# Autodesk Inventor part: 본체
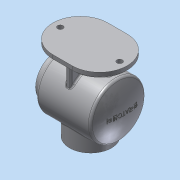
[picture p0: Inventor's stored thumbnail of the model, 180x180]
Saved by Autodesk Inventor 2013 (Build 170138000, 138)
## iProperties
Created: 2016-04
Part Number: 본체
Material: 알루미늄 6061
Document SubType Name: Modeling
Designer: dgall
Density: 1 g/cm^3
Author: dgall
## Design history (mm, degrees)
sketch "스케치1"
  geometry: L1 (-61, 0)-(61, 0); L2 (-61, 27)-(-46, 27); L3 (-46, 27)-(-46, 47); L4 (-46, 47)-(48.145, 47); L5 (-61, 27)-(-61, 38); L6 (-61, 38)-(-49, 38); L7 (-49, 38)-(-49, 50); L8 (-49, 50)-(50.087, 50); A1 r 120 centre (-59, 0) between (61, 0) and (50.087, 50); A2 r 117 centre (-59, 0) between (58, 0) and (48.145, 47); 2 further points
  constraints: 16 end point, 4 parallel, 4 point on circle, 3 perpendicular, 2 centre point, 2 point on line, 1 coincident, 1 concentric, 1 horizontal, 1 horizontal alignment, 1 midpoint, 1 vertical alignment
  dimensions: "d0" = 122 distance of L1.end L1.start; "d11" = 54 diameter of L2 L1; "d12" = 76 diameter of L6 L1; "d13" = 100 diameter of L8 L1; "d14" = 94 diameter of L4 L1; "d16" = 3 distance between parallel lines of L3 L7; "d99" = 120 radius of A1; "d101" = 3 distance of L1.end A2.start
revolve "회전1" sketch "스케치1" stored, may be unused: angle "d18" = 90 deg
node "작업 평면1"
sketch "스케치2"
  geometry: L1 (49.544, 50)-(49.544, -50) reference; C1 r 38 at (-0.456, 0); 1 further point
  constraints: 1 centre point, 1 horizontal alignment
  dimensions: "d104" = 50 distance from line of L1 C1.centre; "d105" = 76 diameter of C1
extrude "돌출1" join sketch "스케치2" distance "d23" = 15; taper "d25" = 0 deg; dims "d24" = 30, "d26" = 0
sketch "스케치13"
  geometry: L1 (61, 27)-(61, -27) reference; L2 (46, 47)-(46, -47) reference; L3 (-48.145, -47)-(46, -47) reference; L4 (61, 0)-(-58, 0); L5 (46, 0)-(46, -47); L6 (46, -47)-(-48.145, -47); A1 r 117 centre (59, 0) between (-48.145, 47) and (-48.145, -47) reference; A2 r 117 centre (59, 0) between (-58, 0) and (-48.145, -47); 1 further point
  constraints: 6 end point, 3 point on circle, 2 collinear, 2 midpoint, 1 centre point, 1 concentric, 1 point on line
revolve "회전4" sketch "스케치13" stored, may be unused: angle "d102" = 90 deg
node "작업 평면2"
sketch "스케치5"
  geometry: L1 (-17.5, 50)-(17.5, 50); L2 (-17.5, -50)-(17.5, -50); C1 r 5 at (54, 0); C2 r 5 at (-54, 0); A1 r 50 centre (-17.5, 0) between (-17.5, 50) and (-17.5, -50); A2 r 50 centre (17.5, 0) between (17.5, -50) and (17.5, 50); 1 further point
  constraints: 4 centre point, 4 end point, 4 horizontal alignment, 4 point on circle, 2 equal radius, 2 tangent, 1 horizontal, 1 parallel
  dimensions: "d34" = 135 dimension on A2 A1; "d36" = 50 radius of A1; "d37" = 17.5 distance of point (0, 0) A2.centre; "d38" = 10 diameter of C1; "d39" = 54 distance of point (0, 0) C1.centre; "d40" = 54 distance of C2.centre point (0, 0)
extrude "돌출3" join sketch "스케치5" distance "d41" = 10; taper "d42" = 0 deg
node "작업 평면3"
  node "작업축2"
sketch "스케치6"
  geometry: L1 (-49.544, -50)-(49.544, -50) reference; L2 (-18.044, -69)-(-68.044, -69) reference; L3 (66.956, -69)-(16.956, -69) reference; L4 (16.956, -69)-(-18.044, -69) reference; L5 (-68.044, -79)-(-68.044, -69) reference; L6 (66.956, -79)-(66.956, -69) reference; L7 (-39.544, -69)-(-36.193, -50); L8 (40.456, -69)-(37.106, -50); L9 (38.456, 65)-(-37.544, 65) reference; 1 further point
  constraints: 4 end point, 4 point on line, 1 equal length
  dimensions: "d44" = 39 horizontal distance of point (-0.544, 0) L7.start; "d45" = 41 horizontal distance of L8.start point (-0.544, 0); "d46" = 100 deg angle of L3 L8
sketch "스케치7"
  geometry: L1 (-50, 69)-(50, 69) reference; L2 (-40, 30)-(-40, 69); L3 (40, 30)-(40, 69); A1 r 50 centre (0, 0) between (-40, 30) and (40, 30) reference; 1 further point
  constraints: 4 end point, 2 point on circle, 2 point on line, 1 horizontal alignment, 1 parallel, 1 perpendicular
  dimensions: "d47" = 40 distance from line of point (0, 0) L2
extrude "돌출4" join sketch "스케치7" stored distance "d48" = 10; taper "d49" = 0 deg
feature "리브1" dims "d50" = 1, "d51" = 10, "d52" = 0, "d53" = 0, "d54" = 1, "d55" = 1
feature "리브2" dims "d56" = 1, "d57" = 10, "d58" = 0, "d59" = 0, "d60" = 1, "d61" = 1
chamfer "모따기1" distance "d62" = 3; stored, may be unused: second distance "d63" = 2, angle "d64" = 45 deg
fillet "모깎기3" dims "d65" = 5
fillet "모깎기5" dims "d67" = 2
chamfer "모따기2" distance "d68" = 1; stored, may be unused: second distance "d69" = 2, angle "d70" = 45 deg
sketch "스케치8"
  geometry: C1 r 38 at (0, 0) reference; 1 further point
  constraints: 1 horizontal alignment
  dimensions: "d71" = 32.5 distance of C1.centre point (-32.5, 0)
hole "구멍1" sketch "스케치8" at (-32.5, 0) diameter "d72" = 3.242; stored, may be unused: countersink angle "d76" = 90 deg, drill point angle "d78" = 118 deg; dims "d73" = 8, "d74" = 4, "d75" = 2, "d77" = 10
fillet "모깎기6" dims "d93" = 3
fillet "모깎기7" dims "d94" = 3
fillet "모깎기8" dims "d95" = 3
fillet "모깎기9" dims "d103" = 2
node "작업 평면5"
sketch "스케치15"
  geometry: C1 r 38 at (0, 0) reference; C2 r 27 at (0, 0); 1 further point
  constraints: 1 centre point, 1 concentric
  dimensions: "d106" = 54 diameter of C2
extrude "돌출5" cut sketch "스케치15" distance "d108" = 30; taper "d109" = 0 deg
chamfer "모따기3" distance "d110" = 1; stored, may be unused: second distance "d111" = 2, angle "d112" = 45 deg
fillet "모깎기10" dims "d113" = 3
sketch "스케치16"
  geometry: C1 r 38 at (0, 0) reference; 2 further points
  constraints: 1 vertical alignment
  dimensions: "d114" = 32.5 distance of point (0, 32.5) C1.centre
hole "구멍3" sketch "스케치16" at (0, 32.5) diameter "d115" = 3.242; stored, may be unused: countersink angle "d119" = 90 deg, drill point angle "d121" = 118 deg; dims "d116" = 8, "d117" = 4, "d118" = 2, "d120" = 10
node "작업 평면7"
  node "작업 평면6"
sketch "스케치17"
  geometry: 2 further points
  constraints: 1 coincident, 1 other
feature "엠보싱1" sketch "스케치17" dims "d0" = 122, "d34" = 135, "d36" = 50, "d37" = 17.5, "d38" = 10, "d39" = 54, "d40" = 54, "d126" = 0.5, "d127" = 0.5 deg
node "솔리드1"
pattern_circular "원형 패턴1" dims angle "d80" = 360 deg
pattern_circular "원형 패턴3" dims angle "d123" = 360 deg
other parameters: "d32" = 79, "d43" = 0, "d125" = -2
